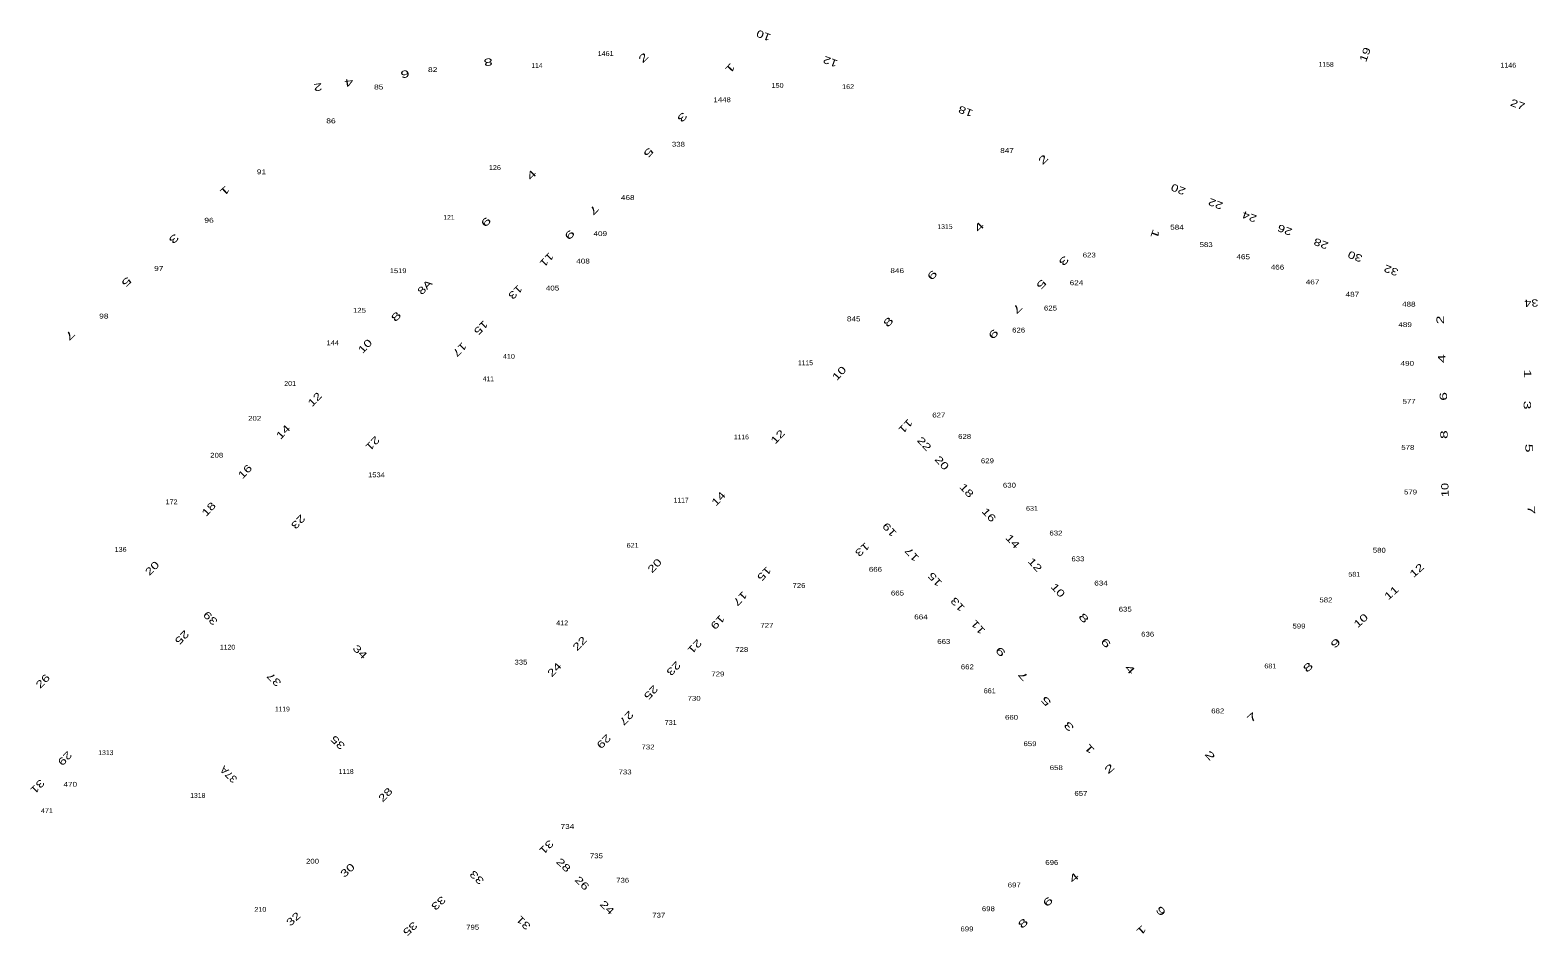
# Model space of a CAD drawing. Extents: x -828673 to -815583, y -1077737 to -1063807.
# Drawn here: x -819548.1 to -819237.8, y -1069113.6 to -1068927.1 of the extents above; entities that cross this region are included whole.
import ezdxf
from ezdxf.enums import TextEntityAlignment as Align

# ---------------------------------------------------------------- set-up
doc = ezdxf.new("R2010")
doc.units = 0
doc.header["$LTSCALE"] = 0.4
doc.layers.add('1', color=7, linetype='Continuous')
doc.layers.add('2', color=7, linetype='Continuous')

msp = doc.modelspace()

# ---------------------------------------------------------------- texts
at = {"layer": '1'}
for s, width, p in [('1461', 1.1, (-819429.658, -1068932.476)), ('82', 1.3, (-819465.237, -1068935.77)), ('1158', 1.05, (-819281.404, -1068934.699)), ('1146', 1.1, (-819243.927, -1068934.868)), ('85', 1.3, (-819476.337, -1068939.359)), ('150', 1.1, (-819394.274, -1068939.026)), ('162', 1.1, (-819379.763, -1068939.277)), ('1448', 1.2, (-819405.677, -1068941.98)), ('86', 1.3, (-819486.171, -1068946.327)), ('338', 1.2, (-819414.676, -1068951.136)), ('847', 1.25, (-819347.062, -1068952.43)), ('91', 1.3, (-819500.461, -1068956.814)), ('126', 1.1, (-819452.434, -1068955.932)), ('468', 1.25, (-819425.104, -1068962.104)), ('96', 1.3, (-819511.261, -1068966.78)), ('409', 1.25, (-819430.75, -1068969.532)), ('1315', 1.05, (-819359.837, -1068968.094)), ('584', 1.25, (-819312.093, -1068968.217)), ('583', 1.2, (-819306.091, -1068971.794)), ('97', 1.3, (-819521.602, -1068976.704)), ('408', 1.25, (-819434.299, -1068975.188)), ('623', 1.2, (-819330.15, -1068973.939)), ('465', 1.25, (-819298.465, -1068974.309)), ('466', 1.25, (-819291.414, -1068976.442)), ('1519', 1.15, (-819472.344, -1068977.171)), ('846', 1.25, (-819369.661, -1068977.162)), ('624', 1.25, (-819332.774, -1068979.649)), ('467', 1.25, (-819284.198, -1068979.493)), ('405', 1.25, (-819440.581, -1068980.751)), ('487', 1.25, (-819275.999, -1068982.02)), ('125', 1.2, (-819480.311, -1068985.321)), ('625', 1.2, (-819338.12, -1068984.867)), ('488', 1.25, (-819264.392, -1068984.056)), ('98', 1.3, (-819532.9, -1068986.516)), ('845', 1.25, (-819378.612, -1068987.093)), ('489', 1.25, (-819265.155, -1068988.27)), ('144', 1.15, (-819485.806, -1068992.009)), ('626', 1.2, (-819344.679, -1068989.395)), ('410', 1.1, (-819449.554, -1068994.81)), ('490', 1.25, (-819264.696, -1068996.244)), ('201', 1.1, (-819494.571, -1069000.381)), ('577', 1.2, (-819264.335, -1069004.061)), ('202', 1.2, (-819501.872, -1069007.56)), ('627', 1.2, (-819361.098, -1069006.887)), ('628', 1.2, (-819355.785, -1069011.284)), ('578', 1.2, (-819264.597, -1069013.544)), ('208', 1.2, (-819509.681, -1069015.161)), ('629', 1.2, (-819351.095, -1069016.304)), ('1534', 1.15, (-819476.81, -1069019.2)), ('630', 1.2, (-819346.569, -1069021.325)), ('579', 1.2, (-819264.039, -1069022.732)), ('172', 1.1, (-819518.966, -1069024.747)), ('631', 1.1, (-819341.921, -1069026.091)), ('632', 1.2, (-819337.001, -1069031.177)), ('136', 1.1, (-819529.456, -1069034.545)), ('621', 1.1, (-819424.098, -1069033.705)), ('580', 1.2, (-819270.46, -1069034.709)), ('666', 1.2, (-819374.141, -1069038.643)), ('633', 1.2, (-819332.475, -1069036.493)), ('634', 1.25, (-819327.72, -1069041.481)), ('581', 1.1, (-819275.609, -1069039.664)), ('726', 1.2, (-819389.876, -1069041.983)), ('665', 1.2, (-819369.608, -1069043.532)), ('582', 1.2, (-819281.446, -1069044.948)), ('635', 1.2, (-819322.742, -1069046.845)), ('412', 1.1, (-819438.596, -1069049.678)), ('727', 1.2, (-819396.47, -1069050.179)), ('664', 1.25, (-819364.765, -1069048.446)), ('599', 1.2, (-819286.989, -1069050.329)), ('663', 1.2, (-819360.073, -1069053.496)), ('636', 1.2, (-819318.118, -1069051.996)), ('1120', 1.05, (-819507.445, -1069054.669)), ('728', 1.2, (-819401.644, -1069055.153)), ('335', 1.2, (-819447.076, -1069057.755)), ('729', 1.2, (-819406.558, -1069060.184)), ('662', 1.2, (-819355.229, -1069058.723)), ('681', 1.1, (-819292.882, -1069058.544)), ('730', 1.2, (-819411.453, -1069065.209)), ('661', 1.1, (-819350.623, -1069063.659)), ('660', 1.2, (-819346.134, -1069069.115)), ('682', 1.2, (-819303.705, -1069067.798)), ('731', 1.1, (-819416.272, -1069070.182)), ('732', 1.2, (-819420.937, -1069075.223)), ('659', 1.2, (-819342.329, -1069074.545)), ('1313', 1.05, (-819532.486, -1069076.391)), ('733', 1.2, (-819425.652, -1069080.365)), ('658', 1.2, (-819336.933, -1069079.476)), ('470', 1.25, (-819539.807, -1069082.902)), ('1318', 1.05, (-819513.57, -1069085.196)), ('657', 1.2, (-819331.861, -1069084.78)), ('471', 1.1, (-819544.613, -1069088.328)), ('734', 1.25, (-819437.514, -1069091.589)), ('735', 1.2, (-819431.554, -1069097.628)), ('200', 1.2, (-819489.961, -1069098.733)), ('696', 1.2, (-819337.847, -1069098.993)), ('736', 1.2, (-819426.152, -1069102.652)), ('697', 1.2, (-819345.573, -1069103.625)), ('210', 1.1, (-819500.706, -1069108.652)), ('737', 1.2, (-819418.728, -1069109.841)), ('698', 1.2, (-819350.9, -1069108.522)), ('795', 1.2, (-819457.015, -1069112.317)), ('699', 1.2, (-819355.307, -1069112.674))]:
    msp.add_text(s, height=1, dxfattribs=dict(at, width=width)).set_placement(p, align=Align.CENTER)
for s, p in [('114', (-819443.78, -1068934.925)), ('121', (-819461.888, -1068966.194)), ('1115', (-819388.525, -1068996.117)), ('411', (-819453.794, -1068999.429)), ('1116', (-819401.717, -1069011.39)), ('1117', (-819414.11, -1069024.403)), ('1119', (-819496.165, -1069067.403)), ('1118', (-819483.043, -1069080.264))]:
    msp.add_text(s, height=1, dxfattribs=at).set_placement(p, align=Align.CENTER)
at = {"layer": '2'}
for s, rotation, width, p in [('10', 158.954, 1.35, (-819396.8772, -1068927.5522)), ('2', 46.135, 1.75, (-819421.3482, -1068933.3457)), ('19', 69.685, 1.35, (-819272.6885, -1068932.4399)), ('6', 188.398, 1.65, (-819471.0495, -1068935.453)), ('8', 188.033, 1.65, (-819453.9212, -1068932.9982)), ('1', 226.85, 1.75, (-819404.5498, -1068934.4776)), ('12', 159.773, 1.35, (-819383.1537, -1068932.9327)), ('2', 188.179, 1.65, (-819488.9413, -1068938.1536)), ('4', 188.305, 1.65, (-819482.5712, -1068937.2246)), ('27', 339.783, 1.35, (-819242.2482, -1068943.162)), ('3', 226.147, 1.75, (-819414.4016, -1068944.5644)), ('18', 159.866, 1.35, (-819355.3203, -1068943.1641)), ('5', 226.275, 1.75, (-819421.3612, -1068951.8371)), ('2', 46.072, 1.75, (-819339.0878, -1068954.3068)), ('4', 46.085, 1.75, (-819444.37, -1068957.4777)), ('1', 222.843, 1.75, (-819508.4975, -1068959.6834)), ('20', 158.728, 1.35, (-819311.5674, -1068959.2225)), ('22', 159.233, 1.35, (-819303.8936, -1068962.2121)), ('6', 45.964, 1.75, (-819453.7377, -1068967.1503)), ('7', 226.673, 1.75, (-819432.6014, -1068963.6539)), ('24', 159.259, 1.35, (-819296.9259, -1068964.8597)), ('3', 222.953, 1.75, (-819518.9895, -1068969.562)), ('9', 225.981, 1.75, (-819437.5935, -1068968.7533)), ('4', 46.228, 1.75, (-819352.2726, -1068968.1798)), ('1', 250.303, 1.65, (-819317.2808, -1068968.8422)), ('26', 159.177, 1.35, (-819289.6449, -1068967.5818)), ('28', 159.426, 1.35, (-819282.2014, -1068970.4048)), ('30', 159.11, 1.35, (-819275.1716, -1068973.053)), ('11', 227.023, 1.4, (-819442.3098, -1068973.9112)), ('3', 226.245, 1.75, (-819335.9002, -1068974.1293)), ('32', 159.358, 1.35, (-819267.7606, -1068975.9092)), ('5', 222.688, 1.75, (-819528.739, -1068978.4282)), ('6', 46.464, 1.75, (-819361.9095, -1068978.0941)), ('5', 226.348, 1.75, (-819340.5252, -1068978.9548)), ('8A', 45.794, 1.35, (-819466.3151, -1068980.5754)), ('13', 226.012, 1.4, (-819448.7413, -1068980.5711)), ('7', 225.898, 1.75, (-819345.4803, -1068983.973)), ('34', 182.252, 1.3, (-819239.206, -1068982.5962)), ('8', 45.789, 1.75, (-819472.2396, -1068986.6295)), ('15', 225.834, 1.4, (-819455.8324, -1068987.9044)), ('8', 46.252, 1.75, (-819370.9544, -1068987.7431)), ('2', 91.381, 1.6, (-819257.1949, -1068986.7681)), ('7', 223.57, 1.75, (-819540.3711, -1068989.4305)), ('10', 46.589, 1.4, (-819478.6128, -1068992.7279)), ('9', 226.212, 1.75, (-819350.3977, -1068989.192)), ('17', 226.185, 1.4, (-819460.2258, -1068992.3993)), ('4', 91.985, 1.6, (-819256.8715, -1068994.7415)), ('10', 46.367, 1.4, (-819381.0584, -1068998.306)), ('1', 271.366, 1.6, (-819240.7093, -1068997.8916)), ('12', 46.062, 1.4, (-819488.9776, -1069003.6799)), ('6', 91.184, 1.6, (-819256.5378, -1069002.5275)), ('3', 271.469, 1.6, (-819240.7457, -1069004.3638)), ('14', 45.999, 1.4, (-819495.4723, -1069010.39)), ('12', 46.221, 1.4, (-819393.7147, -1069011.3799)), ('11', 226.5, 1.4, (-819368.4612, -1069008.1797)), ('8', 91.23, 1.6, (-819256.4075, -1069010.4036)), ('21', 226.192, 1.4, (-819478.1156, -1069011.6933)), ('22', 312.752, 1.4, (-819364.6501, -1069012.8009)), ('5', 271.536, 1.6, (-819240.3997, -1069013.2199)), ('20', 312.466, 1.4, (-819361.0123, -1069016.7386)), ('16', 46.157, 1.4, (-819503.3234, -1069018.54)), ('14', 46.244, 1.4, (-819405.8874, -1069024.1407)), ('18', 312.51, 1.4, (-819355.9205, -1069022.4057)), ('10', 91.197, 1.3, (-819256.2109, -1069021.7997)), ('18', 46.06, 1.4, (-819510.7946, -1069026.2689)), ('7', 272.012, 1.6, (-819239.9101, -1069025.9357)), ('23', 226.192, 1.4, (-819493.4426, -1069027.8633)), ('16', 312.466, 1.4, (-819351.3373, -1069027.4346)), ('19', 132.653, 1.4, (-819370.702, -1069029.4902)), ('14', 312.418, 1.4, (-819346.4512, -1069032.8826)), ('13', 221.797, 1.4, (-819377.3331, -1069033.5198)), ('17', 132.487, 1.4, (-819366.0943, -1069034.5796)), ('20', 45.802, 1.4, (-819522.4331, -1069038.4494)), ('20', 46.364, 1.4, (-819419.0373, -1069037.9011)), ('15', 226.336, 1.4, (-819397.5545, -1069038.5457)), ('12', 312.496, 1.4, (-819341.8599, -1069037.7058)), ('12', 41.971, 1.4, (-819262.2596, -1069038.9193)), ('15', 132.408, 1.4, (-819361.3505, -1069039.7293)), ('17', 226.005, 1.4, (-819402.5045, -1069043.6701)), ('13', 132.402, 1.4, (-819356.6834, -1069044.8812)), ('10', 312.51, 1.4, (-819337.1365, -1069042.9557)), ('11', 41.615, 1.4, (-819267.4791, -1069043.5434)), ('39', 135.729, 1.4, (-819510.4505, -1069047.6875)), ('19', 226.687, 1.4, (-819407.1389, -1069048.5205)), ('11', 132.365, 1.4, (-819352.4928, -1069049.5654)), ('8', 312.656, 1.75, (-819331.8243, -1069048.6793)), ('10', 41.943, 1.4, (-819273.7698, -1069049.2556)), ('25', 225.506, 1.4, (-819517.3544, -1069051.6489)), ('22', 46.233, 1.4, (-819434.4451, -1069053.9368)), ('21', 226.34, 1.4, (-819411.8523, -1069053.5247)), ('6', 312.41, 1.75, (-819327.2678, -1069053.7997)), ('9', 41.242, 1.75, (-819278.9834, -1069053.9147)), ('34', 315.751, 1.4, (-819480.7043, -1069055.6528)), ('9', 132.402, 1.75, (-819347.8311, -1069054.6202)), ('24', 46.292, 1.4, (-819439.6583, -1069059.3097)), ('23', 226.165, 1.4, (-819416.1934, -1069058.0591)), ('4', 312.455, 1.75, (-819322.3147, -1069059.2157)), ('8', 42.004, 1.75, (-819284.6484, -1069058.8426)), ('26', 46.029, 1.4, (-819544.9192, -1069061.6877)), ('37', 135.75, 1.4, (-819497.3727, -1069060.3061)), ('25', 226.34, 1.4, (-819420.8583, -1069062.9817)), ('7', 132.207, 1.75, (-819343.1893, -1069059.6184)), ('5', 132.325, 1.75, (-819338.498, -1069064.7965)), ('27', 226.437, 1.4, (-819425.9056, -1069068.2616)), ('7', 41.96, 1.75, (-819296.161, -1069069.1782)), ('3', 132.594, 1.75, (-819333.7888, -1069070.0061)), ('35', 135.75, 1.4, (-819484.2497, -1069073.2811)), ('29', 225.16, 1.4, (-819430.55, -1069073.0621)), ('1', 132.308, 1.75, (-819329.5438, -1069074.6393)), ('29', 226.322, 1.4, (-819541.4369, -1069076.5525)), ('2', 312.481, 1.75, (-819305.8348, -1069076.984)), ('37A', 135.583, 1.1, (-819506.7221, -1069079.8369)), ('2', 41.902, 1.75, (-819325.5124, -1069079.735)), ('31', 226.137, 1.4, (-819547.0777, -1069082.3513)), ('28', 45.718, 1.4, (-819474.4412, -1069085.0656)), ('31', 225.837, 1.4, (-819442.3493, -1069094.8135)), ('30', 41.889, 1.4, (-819482.2718, -1069100.6667)), ('28', 315.746, 1.4, (-819438.8264, -1069099.556)), ('33', 135.765, 1.4, (-819455.6493, -1069101.0631)), ('26', 315.752, 1.4, (-819435.0223, -1069103.2858)), ('4', 41.355, 1.75, (-819332.816, -1069102.1747)), ('33', 222.205, 1.4, (-819464.5367, -1069106.3148)), ('6', 41.825, 1.75, (-819338.1606, -1069107.1071)), ('32', 42.334, 1.4, (-819493.3941, -1069110.677)), ('24', 315.75, 1.4, (-819429.8553, -1069108.2929)), ('6', 131.725, 1.75, (-819314.8655, -1069107.9997)), ('35', 222.177, 1.4, (-819470.3694, -1069111.5945)), ('31', 135.298, 1.4, (-819446.0509, -1069110.3945)), ('8', 41.987, 1.75, (-819343.2842, -1069111.5718)), ('1', 222, 1.75, (-819319.8927, -1069111.8994))]:
    msp.add_text(s, height=1.5, rotation=rotation, dxfattribs=dict(at, width=width)).set_placement(p, align=Align.CENTER)

doc.saveas('drawing.dxf')
